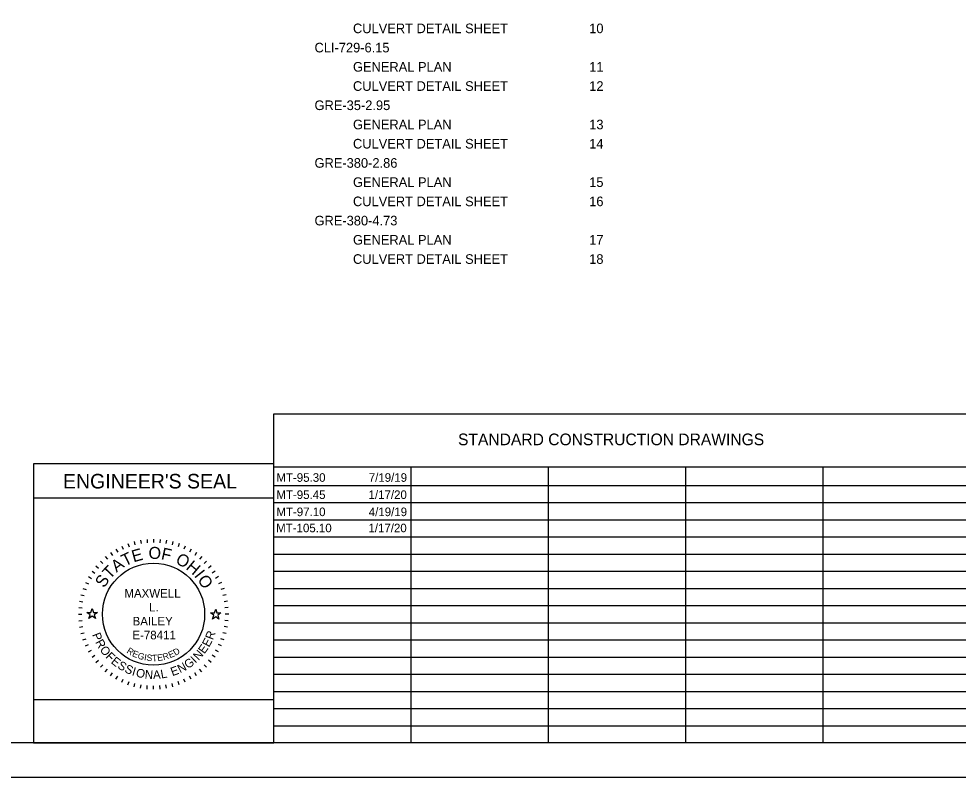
# Model space of a CAD drawing. Extents: x 43.1 to 77.1, y 2.7 to 24.7.
# Drawn here: x 50.67 to 64.35, y 2.66 to 13.71 of the extents above; entities that cross this region are included whole.
import ezdxf

# ---------------------------------------------------------------- set-up
doc = ezdxf.new("R2010")
doc.units = 0
for name, color, linetype in [('SH_Border', 7, 'Continuous'), ('SH_Cut_Line', 7, 'Continuous'), ('SH_Data', 7, 'Continuous'), ('SH_Text', 7, 'Continuous')]:
    doc.layers.add(name, color=color, linetype=linetype)

msp = doc.modelspace()

# ---------------------------------------------------------------- linework, layer by layer
at = {"layer": 'SH_Border'}
msp.add_lwpolyline([(44.631, 24.158), (76.631, 24.158), (76.631, 3.158), (44.631, 3.158)], close=True, dxfattribs=at)
at = {"layer": 'SH_Cut_Line'}
msp.add_lwpolyline([(43.131, 2.658), (77.131, 2.658), (77.131, 24.658), (43.131, 24.658)], close=True, dxfattribs=at)
at = {"layer": 'SH_Data'}
for p, q in [((54.381, 7.95), (67.831, 7.95)), ((54.381, 3.158), (54.381, 7.95)), ((54.381, 7.221), (50.881, 7.221)), ((50.881, 7.221), (50.881, 3.158)), ((54.381, 3.158), (54.381, 7.221)), ((54.381, 3.158), (54.381, 7.221)), ((54.381, 7.179), (67.831, 7.179)), ((56.381, 3.158), (56.381, 7.179)), ((58.381, 3.158), (58.381, 7.179)), ((60.381, 3.158), (60.381, 7.179)), ((62.381, 3.158), (62.381, 7.179)), ((54.381, 6.908), (66.106, 6.908)), ((54.381, 6.721), (50.881, 6.721)), ((54.381, 6.658), (66.106, 6.658)), ((54.381, 6.408), (66.106, 6.408)), ((54.381, 6.158), (66.106, 6.158)), ((52.169, 6.024), (52.19, 5.979)), ((52.257, 6.061), (52.274, 6.014)), ((52.348, 6.09), (52.361, 6.041)), ((52.441, 6.11), (52.45, 6.061)), ((52.536, 6.123), (52.54, 6.073)), ((52.631, 6.127), (52.631, 6.077)), ((52.726, 6.123), (52.722, 6.073)), ((52.821, 6.11), (52.812, 6.061)), ((52.914, 6.09), (52.901, 6.041)), ((53.005, 6.061), (52.988, 6.014)), ((53.093, 6.024), (53.072, 5.979)), ((52.004, 5.929), (52.032, 5.888)), ((52.084, 5.98), (52.109, 5.937)), ((53.178, 5.98), (53.153, 5.937)), ((53.258, 5.929), (53.23, 5.888)), ((54.381, 5.908), (67.831, 5.908)), ((51.858, 5.806), (51.893, 5.771)), ((51.928, 5.871), (51.96, 5.833)), ((53.334, 5.871), (53.302, 5.833)), ((53.404, 5.806), (53.369, 5.771)), ((51.735, 5.66), (51.776, 5.632)), ((51.793, 5.736), (51.831, 5.704)), ((53.469, 5.736), (53.43, 5.704)), ((53.527, 5.66), (53.486, 5.632)), ((54.381, 5.658), (67.831, 5.658)), ((51.64, 5.495), (51.685, 5.474)), ((51.684, 5.58), (51.727, 5.555)), ((53.578, 5.58), (53.535, 5.555)), ((53.622, 5.495), (53.577, 5.474)), ((51.603, 5.407), (51.65, 5.39)), ((53.659, 5.407), (53.612, 5.39)), ((54.381, 5.408), (67.831, 5.408)), ((51.554, 5.223), (51.603, 5.214)), ((51.574, 5.316), (51.623, 5.303)), ((53.687, 5.316), (53.639, 5.303)), ((53.708, 5.223), (53.659, 5.214)), ((51.541, 5.128), (51.591, 5.124)), ((53.72, 5.128), (53.671, 5.124)), ((54.381, 5.158), (67.831, 5.158)), ((51.537, 5.033), (51.587, 5.033)), ((51.541, 4.938), (51.591, 4.942)), ((53.72, 4.938), (53.671, 4.942)), ((53.725, 5.033), (53.675, 5.033)), ((51.554, 4.843), (51.603, 4.852)), ((53.708, 4.843), (53.659, 4.852)), ((54.381, 4.908), (67.831, 4.908)), ((51.574, 4.75), (51.623, 4.763)), ((51.603, 4.659), (51.65, 4.676)), ((53.659, 4.659), (53.612, 4.676)), ((53.687, 4.75), (53.639, 4.763)), ((54.381, 4.658), (67.831, 4.658)), ((51.64, 4.571), (51.685, 4.592)), ((53.622, 4.571), (53.577, 4.592)), ((51.684, 4.486), (51.727, 4.511)), ((51.735, 4.406), (51.776, 4.434)), ((53.527, 4.406), (53.486, 4.434)), ((53.578, 4.486), (53.535, 4.511)), ((54.381, 4.408), (67.831, 4.408)), ((51.793, 4.33), (51.831, 4.362)), ((51.858, 4.26), (51.893, 4.295)), ((53.404, 4.26), (53.369, 4.295)), ((53.469, 4.33), (53.43, 4.362)), ((51.928, 4.195), (51.96, 4.233)), ((52.004, 4.137), (52.032, 4.178)), ((52.084, 4.086), (52.109, 4.129)), ((53.178, 4.086), (53.153, 4.129)), ((53.258, 4.137), (53.23, 4.178)), ((53.334, 4.195), (53.302, 4.233)), ((54.381, 4.158), (67.831, 4.158)), ((52.169, 4.042), (52.19, 4.087)), ((52.257, 4.005), (52.274, 4.052)), ((52.348, 3.977), (52.361, 4.025)), ((52.441, 3.956), (52.45, 4.005)), ((52.536, 3.943), (52.54, 3.993)), ((52.631, 3.939), (52.631, 3.989)), ((52.726, 3.943), (52.722, 3.993)), ((52.821, 3.956), (52.812, 4.005)), ((52.914, 3.977), (52.901, 4.025)), ((53.005, 4.005), (52.988, 4.052)), ((53.093, 4.042), (53.072, 4.087)), ((54.381, 3.908), (67.831, 3.908)), ((54.381, 3.658), (67.831, 3.658)), ((54.381, 3.408), (67.831, 3.408)), ((54.381, 3.158), (50.881, 3.158)), ((54.381, 3.158), (50.881, 3.158))]:
    msp.add_line(p, q, dxfattribs=at)
for points in [[(51.66, 5.058), (51.719, 5.058), (51.737, 5.114), (51.755, 5.058), (51.814, 5.058), (51.767, 5.023), (51.785, 4.968), (51.737, 5.002), (51.69, 4.968), (51.708, 5.023)], [(53.459, 5.051), (53.518, 5.051), (53.536, 5.107), (53.554, 5.051), (53.613, 5.051), (53.565, 5.017), (53.584, 4.961), (53.536, 4.995), (53.489, 4.961), (53.507, 5.017)], [(54.381, 3.158), (54.381, 3.783), (50.881, 3.783), (50.881, 3.158)], [(54.381, 3.158), (54.381, 3.783), (50.881, 3.783), (50.881, 3.158)]]:
    msp.add_lwpolyline(points, close=True, dxfattribs=at)
msp.add_circle((52.631, 5.033), 0.744, dxfattribs=at)

# ---------------------------------------------------------------- texts
for s, height, p in [("ENGINEER'S SEAL", 0.2125, (51.312, 6.864)), ('MAXWELL', 0.125, (52.207, 5.275)), ('L.', 0.125, (52.566, 5.072)), ('BAILEY', 0.125, (52.326, 4.869)), ('E-78411', 0.125, (52.323, 4.666))]:
    msp.add_text(s, height=height, dxfattribs=at).set_placement(p)
for s, height, rotation, p in [('T', 0.175, 25.7167, (52.214, 5.725)), ('E', 0.175, 15.7571, (52.34, 5.787)), ('O', 0.175, 359.7812, (52.558, 5.838)), ('F', 0.175, 347.4362, (52.732, 5.835)), ('O', 0.175, 332.2586, (52.939, 5.781)), ('T', 0.175, 46.4344, (51.996, 5.533)), ('A', 0.175, 36.4747, (52.092, 5.635)), ('H', 0.175, 319.9136, (53.091, 5.698)), ('I', 0.175, 308.367, (53.215, 5.592)), ('S', 0.175, 57.1924, (51.913, 5.406)), ('O', 0.175, 303.1491, (53.264, 5.536)), ('R', 0.125, 69.2322, (53.495, 4.65)), ('P', 0.125, 291.494, (51.734, 4.735)), ('R', 0.125, 298.7311, (51.778, 4.625)), ('E', 0.125, 61.9951, (53.44, 4.544)), ('O', 0.125, 306.4666, (51.841, 4.514)), ('R', 0.0937, 327.8239, (52.231, 4.475)), ('D', 0.0937, 31.466, (52.95, 4.425)), ('N', 0.125, 47.0224, (53.286, 4.352)), ('E', 0.125, 54.758, (53.372, 4.446)), ('F', 0.125, 314.7068, (51.924, 4.406)), ('E', 0.125, 321.4393, (52.002, 4.327)), ('E', 0.0937, 337.7777, (52.311, 4.424)), ('G', 0.0937, 344.2727, (52.391, 4.389)), ('I', 0.0937, 350.6464, (52.489, 4.362)), ('S', 0.0937, 353.7858, (52.525, 4.356)), ('T', 0.0937, 3.0061, (52.612, 4.346)), ('E', 0.0937, 8.9826, (52.692, 4.349)), ('R', 0.0937, 17.6836, (52.779, 4.361)), ('E', 0.0938, 23.3052, (52.87, 4.39)), ('G', 0.125, 35.0469, (53.131, 4.231)), ('I', 0.125, 43.287, (53.24, 4.311)), ('S', 0.125, 328.6764, (52.096, 4.254)), ('S', 0.125, 335.9134, (52.199, 4.193)), ('I', 0.125, 343.1505, (52.308, 4.145)), ('E', 0.125, 20.0742, (52.906, 4.129)), ('N', 0.125, 27.3113, (53.018, 4.171)), ('O', 0.125, 346.8859, (52.366, 4.126)), ('N', 0.125, 355.1261, (52.499, 4.097)), ('A', 0.125, 2.8617, (52.626, 4.088)), ('L', 0.125, 10.0987, (52.745, 4.095))]:
    msp.add_text(s, height=height, rotation=rotation, dxfattribs=at).set_placement(p)
at = {"layer": 'SH_Text'}
for s, height, p in [('CULVERT DETAIL SHEET', 0.14, (55.535, 13.496)), ('10', 0.14, (58.975, 13.496)), ('CLI-729-6.15', 0.14, (54.975, 13.216)), ('GENERAL PLAN', 0.14, (55.535, 12.936)), ('11', 0.14, (58.975, 12.936)), ('CULVERT DETAIL SHEET', 0.14, (55.535, 12.656)), ('12', 0.14, (58.975, 12.656)), ('GRE-35-2.95', 0.14, (54.975, 12.376)), ('GENERAL PLAN', 0.14, (55.535, 12.096)), ('13', 0.14, (58.975, 12.096)), ('CULVERT DETAIL SHEET', 0.14, (55.535, 11.816)), ('14', 0.14, (58.975, 11.816)), ('GRE-380-2.86', 0.14, (54.975, 11.536)), ('GENERAL PLAN', 0.14, (55.535, 11.256)), ('15', 0.14, (58.975, 11.256)), ('CULVERT DETAIL SHEET', 0.14, (55.535, 10.976)), ('16', 0.14, (58.975, 10.976)), ('GRE-380-4.73', 0.14, (54.975, 10.696)), ('GENERAL PLAN', 0.14, (55.535, 10.416)), ('17', 0.14, (58.975, 10.416)), ('CULVERT DETAIL SHEET', 0.14, (55.535, 10.136)), ('18', 0.14, (58.975, 10.136)), ('STANDARD CONSTRUCTION DRAWINGS', 0.17, (57.065, 7.494)), ('MT-95.30', 0.125, (54.42, 6.961)), ('7/19/19', 0.125, (55.765, 6.961)), ('1/17/20', 0.125, (55.762, 6.711)), ('MT-95.45', 0.125, (54.42, 6.711)), ('MT-97.10', 0.125, (54.42, 6.461)), ('4/19/19', 0.125, (55.765, 6.461)), ('MT-105.10', 0.125, (54.417, 6.226)), ('1/17/20', 0.125, (55.76, 6.226))]:
    msp.add_text(s, height=height, dxfattribs=at).set_placement(p)

doc.saveas('drawing.dxf')
